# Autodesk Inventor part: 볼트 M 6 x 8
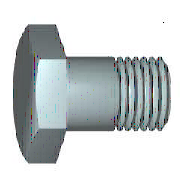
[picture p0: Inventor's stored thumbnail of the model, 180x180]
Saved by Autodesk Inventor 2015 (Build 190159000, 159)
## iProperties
Created: 2012-02
Part Number: 볼트 M 6 x 8
Material: 강철, 연강
Description: 6각 머리 볼트 및 6각 머리 나사
Document SubType Name: Modeling
Standard: KS B 1002
Designer: mduedu
Standards Organization: KS
Language: ko-KR
Size Designation: C  M 6 x 12
Categories: <MemberInstance><Categories><Category DisplayName="조임쇠" InternalName="e4da775c-781d-43d5-af7c-5136215cf5a6" Mnemonic="FSTN"><Category DisplayName="볼트" InternalN
Density: 1 g/cm^3
Appearance: 강철
IsCustomPart: 1
Author: mduedu
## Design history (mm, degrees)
sketch "스케치1"
  geometry: L1 (0, 3)-(8, 3); L2 (8, 3)-(8, 0); L3 (8, 0)-(0, 0); L4 (-2.4, 0)-(14.4, 0) reference; L5 (0, -0.6)-(0, 3.6) reference; L6 (0, 3)-(0, 0)
  constraints: 8 end point, 3 point on line, 1 collinear
  dimensions: "d2" = 6 diameter of L1 L3 (= GD); "d59" = 8 distance between parallel lines of L2 L5 (= NLG)
revolve "본체" sketch "스케치1" stored, may be unused: angle "d12" = 90 deg
sketch "스케치2"
  geometry: L1 (0, 5.774)-(5, 2.887); L2 (5, 2.887)-(5, -2.887); L3 (5, -2.887)-(0, -5.774); L4 (0, -5.774)-(-5, -2.887); L5 (-5, -2.887)-(-5, 2.887); L6 (-5, 2.887)-(0, 5.774); L7 (-7, 0)-(7, 0) reference; L8 (0, 8.083)-(0, -8.083) reference; 2 further points
  constraints: 12 end point, 2 midpoint, 1 coincident, 1 vertical, 11 other
  dimensions: "d11" = 10 distance between parallel lines of L5 L2 (= SW)
extrude "머리" join sketch "스케치2" distance "d3" = 4 (= KOH); taper "d4" = 0 deg
revolve "모따기1" stored, may be unused: angle "d21" = 90 deg
workplane "Work Plane1"
body "Solid1"
feature "스레드" dims "d15" = 9 (= GEL), "d16" = 0
chamfer "모따기2" distance "d6" = 0.61345 (= -0.5 x SPD + 0.5 x GD); stored, may be unused: second distance "d7" = 0.61355 (computed from GUL), angle "d55" = 45 deg
sketch "스케치4"
  geometry: L1 (-3.423, 6)-(-4, 5); L2 (-1.1, 0)-(-0.234, 0); L3 (-4.753, 0)-(0.519, 0) reference; L4 (-4, 6)-(-3.423, 6); L5 (-4, 5)-(-4, 6); L6 (0, 7.2)-(0, -1.2) reference
  constraints: 8 end point, 1 parallel, 1 perpendicular, 1 point on line
  dimensions: "d65" = 10 diameter of L1.end L2 (= SW); "d67" = 30 deg angle of L1 L5 (= ANG1); "d68" = 12 diameter of L4 L2 (= 1.2 x SW); "d69" = 4 distance between parallel lines of L5 L6 (= KOH)
other parameters: "NLG" = 8 [user parameter; used in 1 equation term], "GD" = 6 (= NND) [user parameter; used in 2 equation terms], "BDM" = 6 (= NND) [user parameter], "KOH" = 4 [user parameter; used in 2 equation terms], "GEL" = 9 [user parameter; used in 1 equation term], "SW" = 10 [user parameter; used in 5 equation terms], "SPD" = 4.7731 (= NND - 1.2269 x PTC) [user parameter; used in 1 equation term], "SD2" = 6 (= NND) [user parameter], "SD" = 0 [user parameter], "ANG1" = 30 deg [user parameter; used in 1 equation term], "GAL" = 0.61345 (= 0.61345 x PTC) [user parameter], "GUL" = 0.61345 (= 0.61345 x PTC) [user parameter; used in 1 equation term], "d8" = 0, "RR" = 0.25 [user parameter], "d58" = 0, "RR1" = 0.1 [user parameter], "GD1" = 4.7731 (= THREADDIA - 1.2269 x PTC) [user parameter], "THREADDIA" = 6 [user parameter; used in 1 equation term], "TOA" = 30 deg [user parameter], "PTC" = 1 [user parameter; used in 5 equation terms], "NND" = 6 [user parameter; used in 4 equation terms], "E0" = 11.55 (= 1.155 x SW) [user parameter]
